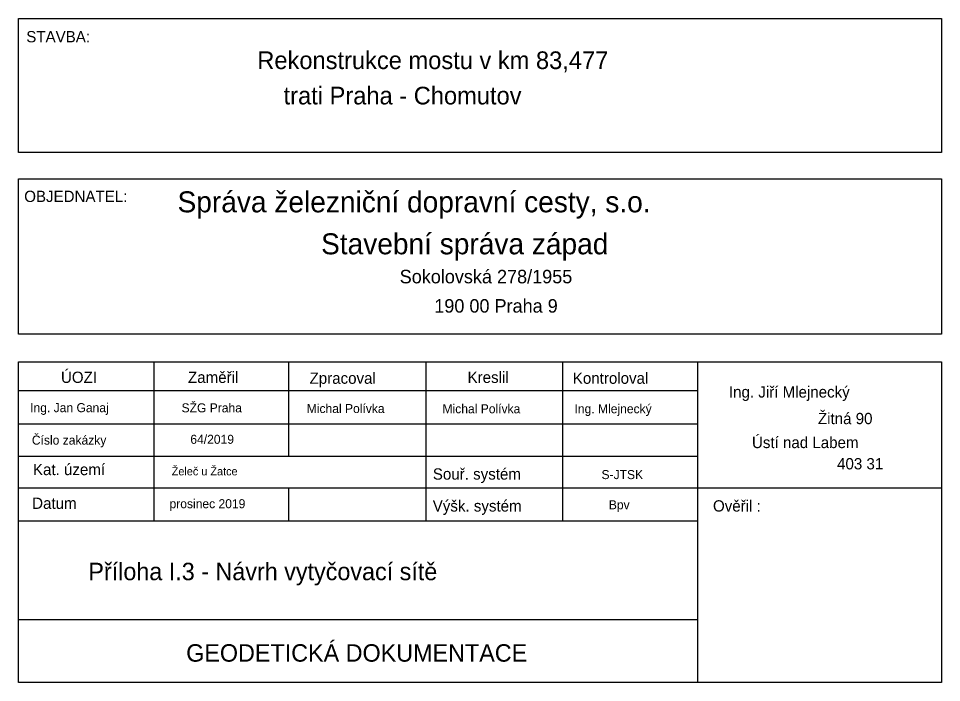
# Model space of a CAD drawing. Extents: x -879530 to -879371, y -1019242 to -1019127.
import ezdxf

# ---------------------------------------------------------------- set-up
doc = ezdxf.new("R2010")
doc.units = 0
doc.layers.add('LEGENDA', color=7, linetype='Continuous')
doc.layers.add('tabulka', color=7, linetype='Continuous')

msp = doc.modelspace()

# ---------------------------------------------------------------- linework, layer by layer
at = {"layer": 'tabulka'}
for p, q in [((-879530.09, -1019186.45), (-879371.44, -1019186.45)), ((-879506.8, -1019186.45), (-879506.8, -1019213.77)), ((-879483.66, -1019186.45), (-879483.66, -1019202.65)), ((-879460.06, -1019186.45), (-879460.06, -1019213.77)), ((-879436.61, -1019186.45), (-879436.61, -1019213.77)), ((-879413.31, -1019241.58), (-879413.31, -1019186.45)), ((-879530.09, -1019191.36), (-879413.31, -1019191.36)), ((-879530.09, -1019197.07), (-879413.31, -1019197.07)), ((-879530.09, -1019202.65), (-879413.31, -1019202.65)), ((-879530.09, -1019208.07), (-879371.44, -1019208.07)), ((-879483.66, -1019208.07), (-879483.66, -1019213.77)), ((-879530.09, -1019213.77), (-879413.31, -1019213.77)), ((-879530.09, -1019230.76), (-879413.31, -1019230.76))]:
    msp.add_line(p, q, dxfattribs=at)
for points in [[(-879530.09, -1019127.36), (-879371.44, -1019127.36), (-879371.44, -1019150.43), (-879530.09, -1019150.43)], [(-879530.09, -1019154.95), (-879371.44, -1019154.95), (-879371.44, -1019181.64), (-879530.09, -1019181.64)]]:
    msp.add_lwpolyline(points, close=True, dxfattribs=at)
msp.add_lwpolyline([(-879371.44, -1019186.45), (-879371.44, -1019241.58), (-879530.09, -1019241.58), (-879530.09, -1019186.45)], dxfattribs=at)

# ---------------------------------------------------------------- texts
at = {"layer": 'LEGENDA'}
for s, p in [('Rekonstrukce mostu v km 83,477', (-879489.04, -1019136.07)), ('    trati Praha - Chomutov', (-879489.04, -1019142.15))]:
    msp.add_text(s, height=3.04, dxfattribs=at).set_placement(p)
at = {"layer": 'tabulka'}
for s, height, p in [('STAVBA:', 1.94, (-879528.75, -1019131.47)), ('OBJEDNATEL:', 1.94, (-879529.1, -1019158.93)), ('Správa železniční dopravní cesty, s.o.', 3.61, (-879502.75, -1019160.71)), ('Stavební správa západ', 3.61, (-879478.08, -1019167.93)), ('Sokolovská 278/1955', 2.32, (-879464.57, -1019172.92)), ('190 00 Praha 9', 2.32, (-879458.62, -1019177.96)), ('ÚOZI', 1.94, (-879522.79, -1019190.05)), ('Zaměřil', 1.94, (-879500.95, -1019190.05)), ('Zpracoval', 1.94, (-879480.06, -1019190.2)), ('Kreslil', 1.94, (-879452.9, -1019190.05)), ('Kontroloval', 1.94, (-879434.81, -1019190.2)), ('Ing. Jiří Mlejnecký', 1.94, (-879407.98, -1019192.57)), ('Ing. Jan Ganaj', 1.552, (-879528.08, -1019195.08)), ('SŽG Praha', 1.552, (-879502.06, -1019195.11)), ('Michal Polívka', 1.552, (-879480.54, -1019195.23)), ('Michal Polívka', 1.552, (-879457.21, -1019195.27)), ('Ing. Mlejnecký', 1.552, (-879434.52, -1019195.27)), ('Žitná 90', 1.94, (-879392.68, -1019197.14)), ('Číslo zakázky', 1.552, (-879527.79, -1019200.66)), ('64/2019', 1.552, (-879500.55, -1019200.52)), ('Ústí nad Labem', 1.94, (-879404.02, -1019201.26)), ('403 31', 1.94, (-879389.39, -1019204.92)), ('Kat. území', 1.94, (-879527.6, -1019205.91)), ('Želeč u Žatce', 1.3968, (-879503.75, -1019205.95)), ('Souř. systém', 1.94, (-879458.87, -1019206.68)), ('S-JTSK', 1.552, (-879429.88, -1019206.59)), ('Datum', 1.94, (-879527.74, -1019211.71)), ('prosinec 2019', 1.552, (-879504.13, -1019211.6)), ('Výšk. systém', 1.94, (-879458.89, -1019212.17)), ('Bpv', 1.552, (-879428.62, -1019211.78)), ('Ověřil :', 1.94, (-879410.72, -1019212.17)), ('Příloha I.3 - Návrh vytyčovací sítě', 3, (-879518.08, -1019223.98)), ('GEODETICKÁ DOKUMENTACE ', 3, (-879501.27, -1019237.99))]:
    msp.add_text(s, height=height, dxfattribs=at).set_placement(p)

doc.saveas('drawing.dxf')
